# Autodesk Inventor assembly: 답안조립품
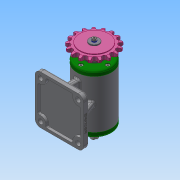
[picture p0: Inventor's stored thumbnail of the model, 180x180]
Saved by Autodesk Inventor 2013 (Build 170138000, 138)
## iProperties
Created: 2019-06
Part Number: 답안조립품
Document SubType Name: Assembly
Designer: Administrator
Author: Administrator
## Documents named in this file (11)
- C:\Users\Administrator\Desktop\490604V1025\답안조립품.iam
- C:\Users\Administrator\Desktop\490604V1025\본체.ipt
- C:\Users\Administrator\Desktop\490604V1025\베어링 6203.ipt
- C:\Users\Administrator\Desktop\490604V1025\볼트 M4.ipt
- C:\Users\Administrator\Desktop\490604V1025\스프로킷.ipt
- C:\Users\Administrator\Desktop\490604V1025\스프링와셔.ipt
- C:\Users\Administrator\Desktop\490604V1025\오일 실 17 30 5.ipt
- C:\Users\Administrator\Desktop\490604V1025\축.ipt
- C:\Users\Administrator\Desktop\490604V1025\커버.ipt
- C:\Users\Administrator\Desktop\490604V1025\키 4x4x12.ipt
- C:\Users\Administrator\Desktop\490604V1025\평와셔.ipt
